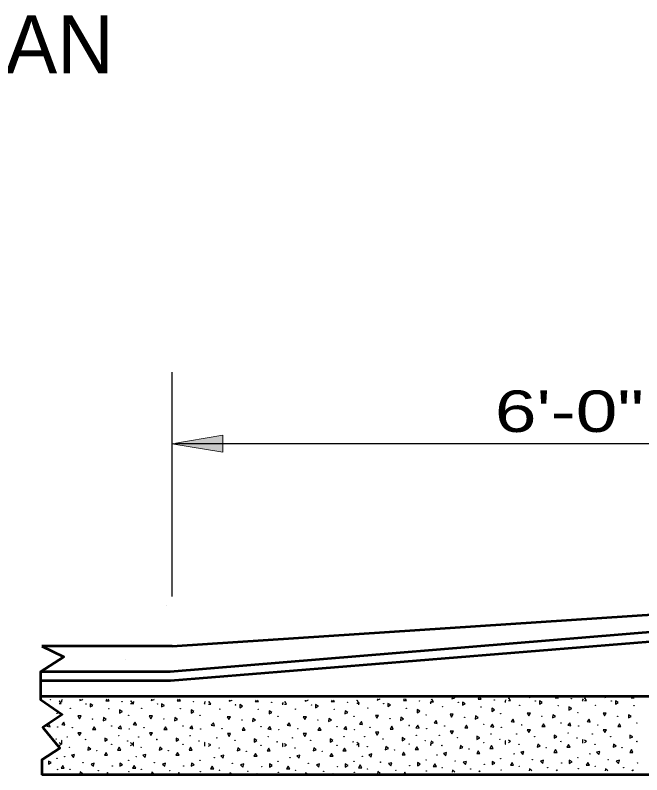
# Model space of a CAD drawing. Extents: x 75.6 to 110.9, y 28 to 50.
# Drawn here: x 98.102 to 100.368, y 39.251 to 42 of the extents above; entities that cross this region are included whole.
import ezdxf
from ezdxf.enums import TextEntityAlignment as Align

# ---------------------------------------------------------------- set-up
doc = ezdxf.new("R2010")
doc.units = 0
doc.header["$LTSCALE"] = 0.06
doc.layers.add('1', color=7, linetype='Continuous', lineweight=25)
doc.layers.add('3', color=7, linetype='Continuous', lineweight=13)

msp = doc.modelspace()

# ---------------------------------------------------------------- hatches: boundary and pattern name
at = {"layer": '3'}
msp.add_hatch(color=256, dxfattribs=at).paths.add_polyline_path([(98.853, 40.47942), (98.853, 40.418), (98.66842, 40.44875), (98.66842, 40.44875)])

# ---------------------------------------------------------------- linework, layer by layer
at = {"layer": '1'}
for p, q in [((98.66925, 39.896), (98.66925, 40.70817)), ((98.68033, 40.45), (101.66942, 40.45)), ((99.96125, 39.535), (99.96042, 39.53033)), ((99.96042, 39.53033), (99.97133, 39.53433)), ((99.97133, 39.53433), (99.97058, 39.535)), ((100.05825, 39.535), (100.05483, 39.52917)), ((100.0665, 39.52917), (100.06317, 39.535)), ((100.23575, 39.535), (100.23492, 39.53033)), ((100.23492, 39.53033), (100.24592, 39.53433)), ((100.24592, 39.53433), (100.24525, 39.535)), ((100.33275, 39.535), (100.32942, 39.52917)), ((100.341, 39.52917), (100.33767, 39.535)), ((98.26225, 39.51875), (98.26033, 39.51558)), ((98.26033, 39.50875), (98.268, 39.50875)), ((98.268, 39.50875), (98.26225, 39.51875)), ((98.27183, 39.523), (98.26783, 39.51617)), ((98.26783, 39.51617), (98.27183, 39.51617)), ((98.33558, 39.52433), (98.33483, 39.51975)), ((98.33483, 39.51975), (98.34575, 39.52375)), ((98.34575, 39.52375), (98.345, 39.52433)), ((98.43258, 39.52433), (98.42925, 39.51858)), ((98.42925, 39.51858), (98.44092, 39.51858)), ((98.44092, 39.51858), (98.43758, 39.52433)), ((98.52075, 39.51875), (98.51883, 39.51558)), ((98.51883, 39.50875), (98.52658, 39.50875)), ((98.52658, 39.50875), (98.52075, 39.51875)), ((98.53033, 39.51558), (98.52642, 39.50875)), ((98.52642, 39.50875), (98.53033, 39.50875)), ((98.59408, 39.52433), (98.59325, 39.51975)), ((98.59325, 39.51975), (98.60425, 39.52375)), ((98.60425, 39.52375), (98.60358, 39.52433)), ((98.69108, 39.52433), (98.68775, 39.51858)), ((98.68775, 39.51858), (98.69942, 39.51858)), ((98.69942, 39.51858), (98.696, 39.52433)), ((98.78883, 39.51558), (98.78492, 39.50875)), ((98.78492, 39.50875), (98.78883, 39.50875)), ((98.803, 39.51592), (98.80117, 39.51267)), ((98.80117, 39.50583), (98.80883, 39.50583)), ((98.80883, 39.50583), (98.803, 39.51592)), ((98.87642, 39.52142), (98.87558, 39.51692)), ((98.87558, 39.51692), (98.88658, 39.52092)), ((98.88658, 39.52092), (98.88583, 39.52142)), ((98.97342, 39.52142), (98.97, 39.51567)), ((98.97, 39.51567), (98.98167, 39.51567)), ((98.98167, 39.51567), (98.97833, 39.52142)), ((99.07117, 39.51267), (99.06725, 39.50583)), ((99.06725, 39.50583), (99.07117, 39.50583)), ((99.07758, 39.51592), (99.07567, 39.51267)), ((99.07567, 39.50583), (99.08342, 39.50583)), ((99.08342, 39.50583), (99.07758, 39.51592)), ((99.15092, 39.52142), (99.15017, 39.51692)), ((99.15017, 39.51692), (99.16108, 39.52092)), ((99.16108, 39.52092), (99.16042, 39.52142)), ((99.24792, 39.52142), (99.24458, 39.51567)), ((99.24458, 39.51567), (99.25625, 39.51567)), ((99.25625, 39.51567), (99.25292, 39.52142)), ((99.33867, 39.52033), (99.33683, 39.51717)), ((99.33683, 39.51033), (99.3445, 39.51033)), ((99.3445, 39.51033), (99.33867, 39.52033)), ((99.34567, 39.51267), (99.34175, 39.50583)), ((99.34175, 39.50583), (99.34567, 39.50583)), ((99.412, 39.526), (99.41125, 39.52133)), ((99.41125, 39.52133), (99.42225, 39.52533)), ((99.42225, 39.52533), (99.4215, 39.526)), ((99.509, 39.526), (99.50567, 39.52017)), ((99.50567, 39.52017), (99.51733, 39.52017)), ((99.51733, 39.52017), (99.514, 39.526)), ((99.60683, 39.51717), (99.60283, 39.51033)), ((99.60283, 39.51033), (99.60683, 39.51033)), ((99.60875, 39.52492), (99.60683, 39.52167)), ((99.60683, 39.51483), (99.61458, 39.51483)), ((99.61458, 39.51483), (99.60875, 39.52492)), ((99.68208, 39.53042), (99.68125, 39.52592)), ((99.68125, 39.52592), (99.69225, 39.52992)), ((99.69225, 39.52992), (99.69158, 39.53042)), ((99.77908, 39.53042), (99.77575, 39.52467)), ((99.77575, 39.52467), (99.78742, 39.52467)), ((99.78742, 39.52467), (99.784, 39.53042)), ((99.87683, 39.52167), (99.87292, 39.51483)), ((99.87292, 39.51483), (99.87683, 39.51483)), ((99.88783, 39.52933), (99.88592, 39.52617)), ((99.88592, 39.51933), (99.89358, 39.51933)), ((99.89358, 39.51933), (99.88783, 39.52933)), ((100.05483, 39.52917), (100.0665, 39.52917)), ((100.15592, 39.52617), (100.152, 39.51933)), ((100.152, 39.51933), (100.15592, 39.51933)), ((100.16242, 39.52933), (100.1605, 39.52617)), ((100.1605, 39.51933), (100.16825, 39.51933)), ((100.16825, 39.51933), (100.16242, 39.52933)), ((100.32942, 39.52917), (100.341, 39.52917)), ((98.2695, 39.37475), (98.26942, 39.36308)), ((98.2695, 39.37475), (98.26942, 39.36308)), ((98.27183, 39.37333), (98.2695, 39.37475)), ((98.27183, 39.37333), (98.2695, 39.37475)), ((99.6045, 39.369), (99.60442, 39.35733)), ((99.6045, 39.369), (99.60442, 39.35733)), ((99.60683, 39.36758), (99.6045, 39.369)), ((99.60683, 39.36758), (99.6045, 39.369)), ((99.87458, 39.37342), (99.8745, 39.36175)), ((99.87458, 39.37342), (99.8745, 39.36175)), ((99.87683, 39.37208), (99.87458, 39.37342)), ((99.87683, 39.37208), (99.87458, 39.37342)), ((100.15358, 39.378), (100.15358, 39.36633)), ((100.15358, 39.378), (100.15358, 39.36633)), ((100.15592, 39.37658), (100.15358, 39.378)), ((100.15592, 39.37658), (100.15358, 39.378)), ((98.26942, 39.36308), (98.27183, 39.36442)), ((98.26942, 39.36308), (98.27183, 39.36442)), ((98.528, 39.36733), (98.528, 39.35567)), ((98.528, 39.36733), (98.528, 39.35567)), ((98.53033, 39.366), (98.528, 39.36733)), ((98.53033, 39.366), (98.528, 39.36733)), ((98.528, 39.35567), (98.53033, 39.357)), ((98.528, 39.35567), (98.53033, 39.357)), ((98.78658, 39.36733), (98.7865, 39.35567)), ((98.78658, 39.36733), (98.7865, 39.35567)), ((98.7865, 39.35567), (98.78883, 39.357)), ((98.7865, 39.35567), (98.78883, 39.357)), ((98.78883, 39.366), (98.78658, 39.36733)), ((98.78883, 39.366), (98.78658, 39.36733)), ((99.06883, 39.36442), (99.06883, 39.35275)), ((99.06883, 39.36442), (99.06883, 39.35275)), ((99.07117, 39.36308), (99.06883, 39.36442)), ((99.07117, 39.36308), (99.06883, 39.36442)), ((99.06883, 39.35275), (99.07117, 39.35417)), ((99.06883, 39.35275), (99.07117, 39.35417)), ((99.34342, 39.36442), (99.34333, 39.35275)), ((99.34342, 39.36442), (99.34333, 39.35275)), ((99.34333, 39.35275), (99.34567, 39.35417)), ((99.34333, 39.35275), (99.34567, 39.35417)), ((99.34567, 39.36308), (99.34342, 39.36442)), ((99.34567, 39.36308), (99.34342, 39.36442)), ((99.60442, 39.35733), (99.60683, 39.35867)), ((99.60442, 39.35733), (99.60683, 39.35867)), ((99.8745, 39.36175), (99.87683, 39.36317)), ((99.8745, 39.36175), (99.87683, 39.36317)), ((100.15358, 39.36633), (100.15592, 39.36767)), ((100.15358, 39.36633), (100.15592, 39.36767)), ((98.198, 39.25075), (98.198, 39.305))]:
    msp.add_line(p, q, dxfattribs=at)
at = {"layer": '1', "lineweight": 53}
for p, q in [((98.66925, 39.71683), (101.66942, 39.91467)), ((101.66942, 39.87133), (98.662, 39.62308)), ((101.67208, 39.83542), (98.663, 39.59125)), ((98.66925, 39.71683), (98.198, 39.71683)), ((98.662, 39.62308), (98.193, 39.62308)), ((98.663, 39.59125), (98.193, 39.59125)), ((98.193, 39.53508), (102.29183, 39.53508)), ((102.29183, 39.25075), (98.198, 39.25075))]:
    msp.add_line(p, q, dxfattribs=at)
msp.add_lwpolyline([(98.198, 39.71683), (98.27783, 39.678), (98.193, 39.62367), (98.193, 39.52358), (98.271, 39.46925), (98.20142, 39.42167), (98.26258, 39.347), (98.198, 39.305), (98.198, 39.25075)], dxfattribs=at)
at = {"layer": '1'}
for points in [[(98.37275, 39.49617), (98.38283, 39.502), (98.37283, 39.50783)], [(98.63125, 39.49617), (98.64133, 39.502), (98.63125, 39.50783)], [(99.44925, 39.49775), (99.45925, 39.50358), (99.44925, 39.50942)], [(99.71925, 39.50225), (99.72933, 39.50808), (99.71925, 39.514)], [(99.99833, 39.50675), (100.00842, 39.51258), (99.99842, 39.51842)], [(100.27292, 39.50675), (100.283, 39.51258), (100.27292, 39.51842)], [(98.47908, 39.47383), (98.48925, 39.47967), (98.47925, 39.48558)], [(98.73758, 39.47383), (98.74767, 39.47967), (98.73767, 39.48558)], [(98.91358, 39.49325), (98.92358, 39.49908), (98.91358, 39.505)], [(99.01992, 39.471), (99.03, 39.47675), (99.02, 39.48267)], [(99.18808, 39.49325), (99.19825, 39.49908), (99.18817, 39.505)], [(99.29442, 39.471), (99.30458, 39.47675), (99.29458, 39.48267)], [(99.55558, 39.47542), (99.56558, 39.48133), (99.55558, 39.48717)], [(99.82558, 39.48), (99.83567, 39.48575), (99.82567, 39.49167)], [(100.10467, 39.48442), (100.11483, 39.49033), (100.10483, 39.49617)], [(98.33383, 39.45367), (98.33958, 39.46375), (98.328, 39.46375)], [(98.4195, 39.44608), (98.43, 39.451), (98.42058, 39.45767)], [(98.59225, 39.45367), (98.59817, 39.46375), (98.5865, 39.46375)], [(98.678, 39.44608), (98.68858, 39.451), (98.679, 39.45767)], [(98.87458, 39.45075), (98.88042, 39.46083), (98.86883, 39.46083)], [(98.96025, 39.44317), (98.97083, 39.44808), (98.96133, 39.45475)], [(99.14917, 39.45075), (99.155, 39.46083), (99.14333, 39.46083)], [(99.23483, 39.44317), (99.24542, 39.44808), (99.23592, 39.45475)], [(99.41025, 39.45525), (99.41608, 39.46533), (99.40442, 39.46533)], [(99.49592, 39.44767), (99.5065, 39.45258), (99.497, 39.45925)], [(99.68025, 39.45975), (99.68617, 39.46983), (99.6745, 39.46983)], [(99.766, 39.45217), (99.77658, 39.45708), (99.767, 39.46375)], [(99.89558, 39.44342), (99.90708, 39.44142), (99.90317, 39.45233)], [(99.95942, 39.46425), (99.96525, 39.47433), (99.95358, 39.47433)], [(100.04508, 39.45667), (100.05558, 39.46158), (100.04617, 39.46825)], [(100.17025, 39.44342), (100.18158, 39.44142), (100.17767, 39.45233)], [(100.23392, 39.46425), (100.23983, 39.47433), (100.22817, 39.47433)], [(100.31958, 39.45667), (100.33025, 39.46158), (100.32067, 39.46825)], [(98.21608, 39.42683), (98.22758, 39.42483), (98.22358, 39.43575)], [(98.27, 39.43283), (98.2815, 39.43083), (98.27758, 39.44175)], [(98.38125, 39.41475), (98.39283, 39.41475), (98.387, 39.42483)], [(98.47458, 39.41942), (98.48608, 39.41742), (98.48217, 39.42833)], [(98.52858, 39.43283), (98.54, 39.43083), (98.536, 39.44175)], [(98.63967, 39.41475), (98.65133, 39.41475), (98.64558, 39.42483)], [(98.73317, 39.41942), (98.74458, 39.41742), (98.74058, 39.42833)], [(98.81083, 39.43), (98.82225, 39.428), (98.81833, 39.43883)], [(99.01542, 39.41658), (99.02692, 39.41458), (99.02292, 39.4255)], [(99.08542, 39.43), (99.09683, 39.428), (99.09292, 39.43883)], [(99.29, 39.41658), (99.30142, 39.41458), (99.2975, 39.4255)], [(99.3465, 39.43442), (99.35792, 39.43242), (99.354, 39.44333)], [(99.45758, 39.41633), (99.46925, 39.41633), (99.4635, 39.42642)], [(99.55108, 39.421), (99.56258, 39.419), (99.55858, 39.43)], [(99.61658, 39.439), (99.628, 39.437), (99.624, 39.44783)], [(99.72767, 39.42092), (99.73933, 39.42092), (99.73358, 39.431)], [(99.82117, 39.42558), (99.83258, 39.42358), (99.82858, 39.4345)], [(100.00683, 39.42533), (100.01842, 39.42533), (100.01258, 39.43542)], [(100.10025, 39.43), (100.11167, 39.428), (100.10775, 39.439)], [(100.28133, 39.42533), (100.293, 39.42533), (100.28725, 39.43542)], [(98.33425, 39.39275), (98.34008, 39.40292), (98.32842, 39.40292)], [(98.59275, 39.39275), (98.59858, 39.40292), (98.58692, 39.40292)], [(98.875, 39.38992), (98.88092, 39.4), (98.86925, 39.4)], [(98.922, 39.41192), (98.93358, 39.41192), (98.92783, 39.422)], [(99.14958, 39.38992), (99.15542, 39.4), (99.14383, 39.4)], [(99.19658, 39.41192), (99.20825, 39.41192), (99.20242, 39.422)], [(99.41067, 39.39433), (99.41658, 39.4045), (99.40492, 39.4045)], [(99.68075, 39.39892), (99.68658, 39.409), (99.67492, 39.409)], [(99.95983, 39.40333), (99.96567, 39.4135), (99.954, 39.4135)], [(100.23442, 39.40333), (100.24025, 39.4135), (100.22858, 39.4135)], [(98.42517, 39.37225), (98.43525, 39.37808), (98.42525, 39.38392)], [(98.68358, 39.37225), (98.69375, 39.37808), (98.68367, 39.38392)], [(98.96592, 39.36933), (98.976, 39.37517), (98.966, 39.381)], [(99.2405, 39.36933), (99.25058, 39.37517), (99.24058, 39.381)], [(99.50158, 39.37383), (99.51167, 39.37967), (99.50158, 39.3855)], [(99.77158, 39.37833), (99.78175, 39.38417), (99.77167, 39.39)], [(100.05075, 39.38283), (100.06083, 39.38867), (100.05083, 39.3945)], [(100.32525, 39.38283), (100.33542, 39.38867), (100.32533, 39.3945)], [(98.364, 39.33992), (98.37492, 39.34392), (98.366, 39.35133)], [(98.47192, 39.34017), (98.48358, 39.34017), (98.47775, 39.35025)], [(98.6225, 39.33992), (98.63342, 39.34392), (98.62458, 39.35133)], [(98.73042, 39.34017), (98.742, 39.34017), (98.73625, 39.35025)], [(98.90483, 39.337), (98.91575, 39.341), (98.90683, 39.34842)], [(99.01267, 39.33733), (99.02433, 39.33733), (99.01858, 39.34733)], [(99.17933, 39.337), (99.19025, 39.341), (99.18142, 39.34842)], [(99.28725, 39.33733), (99.29892, 39.33733), (99.29308, 39.34733)], [(99.44042, 39.3415), (99.45142, 39.3455), (99.4425, 39.353)], [(99.54833, 39.34175), (99.56, 39.34175), (99.55425, 39.35183)], [(99.7105, 39.346), (99.72142, 39.35), (99.71258, 39.35742)], [(99.81842, 39.34633), (99.83, 39.34633), (99.82425, 39.35633)], [(99.98958, 39.3505), (100.00058, 39.3545), (99.99158, 39.362)], [(100.05, 39.33192), (100.06158, 39.33192), (100.05583, 39.342)], [(100.0975, 39.35075), (100.10917, 39.35075), (100.10333, 39.36083)], [(100.26417, 39.3505), (100.27508, 39.3545), (100.26625, 39.362)], [(100.32458, 39.33192), (100.33625, 39.33192), (100.33042, 39.342)], [(98.31283, 39.31358), (98.31583, 39.32475), (98.30458, 39.32175)], [(98.42442, 39.32133), (98.436, 39.32133), (98.43025, 39.33133)], [(98.57133, 39.31358), (98.57433, 39.32475), (98.56308, 39.32175)], [(98.68292, 39.32133), (98.69458, 39.32133), (98.68875, 39.33133)], [(98.85358, 39.31067), (98.85658, 39.32192), (98.84542, 39.31892)], [(98.96525, 39.31833), (98.97683, 39.31833), (98.971, 39.32842)], [(99.12825, 39.31067), (99.13125, 39.32192), (99.11992, 39.31892)], [(99.23975, 39.31833), (99.25142, 39.31833), (99.24558, 39.32842)], [(99.38925, 39.31517), (99.39225, 39.32633), (99.381, 39.32333)], [(99.50083, 39.32292), (99.5125, 39.32292), (99.50667, 39.333)], [(99.65933, 39.31967), (99.66233, 39.33092), (99.65108, 39.32792)], [(99.77092, 39.32733), (99.78258, 39.32733), (99.77675, 39.33742)], [(99.93842, 39.32417), (99.94142, 39.33533), (99.93025, 39.33233)], [(100.213, 39.32417), (100.216, 39.33533), (100.20475, 39.33233)], [(98.22158, 39.289), (98.23175, 39.29475), (98.22167, 39.30058)], [(98.38425, 39.2815), (98.38725, 39.29275), (98.37592, 39.28975)], [(98.48025, 39.28158), (98.49025, 39.28733), (98.48025, 39.29317)], [(98.64267, 39.2815), (98.64567, 39.29275), (98.63442, 39.28975)], [(98.73867, 39.28158), (98.74883, 39.28733), (98.73875, 39.29317)], [(98.925, 39.27858), (98.928, 39.28992), (98.91675, 39.28692)], [(99.021, 39.27867), (99.03108, 39.28442), (99.021, 39.29033)], [(99.19958, 39.27858), (99.20258, 39.28992), (99.19125, 39.28692)], [(99.29558, 39.27867), (99.30558, 39.28442), (99.29558, 39.29033)], [(99.34392, 39.27633), (99.35558, 39.27633), (99.34975, 39.28633)], [(99.46058, 39.28308), (99.46358, 39.29433), (99.45242, 39.29133)], [(99.55658, 39.28317), (99.56675, 39.289), (99.55667, 39.29475)], [(99.61392, 39.28083), (99.62558, 39.28083), (99.61983, 39.29092)], [(99.73067, 39.28758), (99.73367, 39.29892), (99.72242, 39.29592)], [(99.82667, 39.28767), (99.83683, 39.29342), (99.82675, 39.29933)], [(99.893, 39.28533), (99.90467, 39.28533), (99.89892, 39.29533)], [(100.00983, 39.29208), (100.01283, 39.30333), (100.00158, 39.30033)], [(100.10583, 39.29217), (100.11592, 39.298), (100.10583, 39.30375)], [(100.16758, 39.28533), (100.17925, 39.28533), (100.17342, 39.29533)], [(100.28433, 39.29208), (100.28733, 39.30333), (100.27608, 39.30033)], [(98.26742, 39.27475), (98.27908, 39.27475), (98.27325, 39.28475)], [(98.52592, 39.27475), (98.53758, 39.27475), (98.53183, 39.28475)], [(98.80825, 39.27183), (98.81992, 39.27183), (98.81408, 39.28192)], [(99.08283, 39.27183), (99.09442, 39.27183), (99.08858, 39.28192)]]:
    msp.add_lwpolyline(points, close=True, dxfattribs=at)
for points in [[(99.60683, 39.36317), (99.61458, 39.36767), (99.60683, 39.37208)], [(99.88592, 39.36767), (99.89367, 39.37217), (99.88592, 39.37658)], [(100.1605, 39.36767), (100.16825, 39.37217), (100.1605, 39.37658)], [(98.26033, 39.357), (98.26808, 39.36158), (98.26033, 39.366)], [(98.51883, 39.357), (98.52658, 39.36158), (98.51883, 39.366)], [(98.80117, 39.35417), (98.80892, 39.35867), (98.80117, 39.36308)], [(99.07567, 39.35417), (99.08342, 39.35867), (99.07567, 39.36308)], [(99.33683, 39.35867), (99.34458, 39.36317), (99.33683, 39.36758)], [(98.345, 39.25433), (98.33683, 39.26125), (98.33558, 39.25433)], [(98.345, 39.25433), (98.33683, 39.26125), (98.33558, 39.25433)], [(98.43758, 39.25433), (98.43508, 39.25867), (98.43258, 39.25433)], [(98.60358, 39.25433), (98.59533, 39.26125), (98.59408, 39.25433)], [(98.60358, 39.25433), (98.59533, 39.26125), (98.59408, 39.25433)], [(98.696, 39.25433), (98.69358, 39.25867), (98.69108, 39.25433)], [(98.88583, 39.25142), (98.87758, 39.25833), (98.87642, 39.25142)], [(98.88583, 39.25142), (98.87758, 39.25833), (98.87642, 39.25142)], [(99.16042, 39.25142), (99.15225, 39.25833), (99.15092, 39.25142)], [(99.16042, 39.25142), (99.15225, 39.25833), (99.15092, 39.25142)], [(99.4215, 39.256), (99.41325, 39.26283), (99.412, 39.256)], [(99.4215, 39.256), (99.41325, 39.26283), (99.412, 39.256)], [(99.514, 39.256), (99.51158, 39.26025), (99.509, 39.256)], [(99.69158, 39.26042), (99.68333, 39.26733), (99.68208, 39.26042)], [(99.69158, 39.26042), (99.68333, 39.26733), (99.68208, 39.26042)], [(99.784, 39.26042), (99.78158, 39.26475), (99.77908, 39.26042)], [(99.97058, 39.265), (99.96242, 39.27183), (99.96125, 39.265)], [(99.97058, 39.265), (99.96242, 39.27183), (99.96125, 39.265)], [(100.06317, 39.265), (100.06067, 39.26925), (100.05825, 39.265)], [(100.24525, 39.265), (100.237, 39.27183), (100.23575, 39.265)], [(100.24525, 39.265), (100.237, 39.27183), (100.23575, 39.265)], [(100.33767, 39.265), (100.33525, 39.26925), (100.33275, 39.265)], [(98.97833, 39.25142), (98.97592, 39.25575), (98.97342, 39.25142)], [(99.25292, 39.25142), (99.25042, 39.25575), (99.24792, 39.25142)]]:
    msp.add_lwpolyline(points, dxfattribs=at)
for centre in [(98.22961, 39.52318), (98.35764, 39.50685), (98.48816, 39.51578), (98.61614, 39.50685), (98.74666, 39.51578), (99.02896, 39.51288), (99.30351, 39.51288), (99.43409, 39.50845), (99.56461, 39.51738), (99.70414, 39.51295), (99.83466, 39.52188), (99.98324, 39.51745), (100.11376, 39.52638), (100.25779, 39.51745), (98.30074, 39.49124), (98.44019, 39.49013), (98.55924, 39.49124), (98.69869, 39.49013), (98.84154, 39.48834), (98.89844, 39.50395), (98.98099, 39.48723), (99.11609, 39.48834), (99.17299, 39.50395), (99.25554, 39.48723), (99.37719, 39.49284), (99.51664, 39.49173), (99.64724, 39.49734), (99.78669, 39.49623), (99.92634, 39.50184), (100.06579, 39.50073), (100.20089, 39.50184), (100.34034, 39.50073), (98.25306, 39.47299), (98.38106, 39.4522), (98.51161, 39.46559), (98.63956, 39.4522), (98.77011, 39.46559), (99.05241, 39.46269), (99.32696, 39.46269), (99.45751, 39.4538), (99.58806, 39.46719), (99.72756, 39.4583), (99.85811, 39.47169), (100.00666, 39.4628), (100.13721, 39.47619), (100.28121, 39.4628), (98.25528, 39.42389), (98.45025, 39.42765), (98.70875, 39.42765), (98.92186, 39.4493), (98.99105, 39.42475), (99.19641, 39.4493), (99.2656, 39.42475), (99.38502, 39.42255), (99.5267, 39.42925), (99.65507, 39.42705), (99.79675, 39.43375), (99.86033, 39.42259), (99.93417, 39.43155), (100.07585, 39.43825), (100.13943, 39.42709), (100.20872, 39.43155), (100.3504, 39.43825), (98.21735, 39.39934), (98.30857, 39.42095), (98.51384, 39.41649), (98.56707, 39.42095), (98.77233, 39.41649), (98.84937, 39.41805), (99.05463, 39.41359), (99.12392, 39.41805), (99.32918, 39.41359), (99.59028, 39.41809), (99.8224, 39.39804), (99.9152, 39.39809), (100.1015, 39.40254), (100.18975, 39.39809), (98.2497, 39.38038), (98.2896, 39.38749), (98.35541, 39.37856), (98.4759, 39.39194), (98.50826, 39.37298), (98.5481, 39.38749), (98.61391, 39.37856), (98.7344, 39.39194), (98.76676, 39.37298), (98.8304, 39.38459), (98.89621, 39.37566), (99.0167, 39.38904), (99.04905, 39.37008), (99.10495, 39.38459), (99.17076, 39.37566), (99.29125, 39.38904), (99.32361, 39.37008), (99.36605, 39.38909), (99.43186, 39.38016), (99.55235, 39.39354), (99.5847, 39.37458), (99.6361, 39.39359), (99.70191, 39.38466), (99.85475, 39.37908), (99.98101, 39.38916), (100.07585, 39.37131), (100.13385, 39.38358), (100.25556, 39.38916), (100.3504, 39.37131), (98.29851, 39.35068), (98.45025, 39.36071), (98.55701, 39.35068), (98.70875, 39.36071), (98.83931, 39.34778), (98.99105, 39.35781), (99.11386, 39.34778), (99.2656, 39.35781), (99.37496, 39.35228), (99.47315, 39.33999), (99.5267, 39.36231), (99.64501, 39.35678), (99.7432, 39.34449), (99.79675, 39.36681), (99.92411, 39.36128), (100.0223, 39.34899), (100.19866, 39.36128), (100.29685, 39.34899), (98.28067, 39.3161), (98.3967, 39.33839), (98.53917, 39.3161), (98.6552, 39.33839), (98.82147, 39.3132), (98.9375, 39.33549), (99.09602, 39.3132), (99.21205, 39.33549), (99.35712, 39.3177), (99.62717, 39.3222), (99.90627, 39.3267), (100.13721, 39.31331), (100.18082, 39.3267), (98.25306, 39.31011), (98.34648, 39.29488), (98.51161, 39.30271), (98.60498, 39.29488), (98.77011, 39.30271), (98.88728, 39.29198), (99.05241, 39.29981), (99.16183, 39.29198), (99.32696, 39.29981), (99.42293, 39.29648), (99.58806, 39.30431), (99.69298, 39.30098), (99.79898, 39.28872), (99.85811, 39.30881), (99.97208, 39.30548), (100.07808, 39.29322), (100.24663, 39.30548), (100.35263, 39.29322), (98.25416, 39.26995), (98.29963, 39.27035), (98.40228, 39.26588), (98.45248, 39.28262), (98.51271, 39.26255), (98.55813, 39.27035), (98.66078, 39.26588), (98.71098, 39.28262), (98.77121, 39.26255), (98.84043, 39.26745), (98.94308, 39.26298), (98.99328, 39.27972), (99.05351, 39.25965), (99.11498, 39.26745), (99.21763, 39.26298), (99.26783, 39.27972), (99.32806, 39.25965), (99.37609, 39.27195), (99.47873, 39.26748), (99.52893, 39.28422), (99.58916, 39.26415), (99.64613, 39.27645), (99.74878, 39.27198), (99.85921, 39.26865), (99.92523, 39.28095), (100.02788, 39.27648), (100.13831, 39.27315), (100.19978, 39.28095), (100.30243, 39.27648)]:
    msp.add_circle(centre, 0.000647, dxfattribs=at)
at = {"layer": '3'}
for p, q in [((98.64708, 39.865), (98.64717, 39.865)), ((98.49942, 39.66917), (98.4995, 39.66917))]:
    msp.add_line(p, q, dxfattribs=at)
msp.add_lwpolyline([(98.853, 40.47942), (98.853, 40.418), (98.66842, 40.44875), (98.66842, 40.44875)], close=True, dxfattribs=at)

# ---------------------------------------------------------------- texts
at = {"layer": '1'}
msp.add_text('PLAN', height=0.2109, dxfattribs=at).set_placement((98.08896, 41.789), align=Align.CENTER)
at = {"layer": '1', "width": 1.35}
msp.add_text('6\'-0"', height=0.15, dxfattribs=at).set_placement((100.10646, 40.49167), align=Align.CENTER)

doc.saveas('drawing.dxf')
